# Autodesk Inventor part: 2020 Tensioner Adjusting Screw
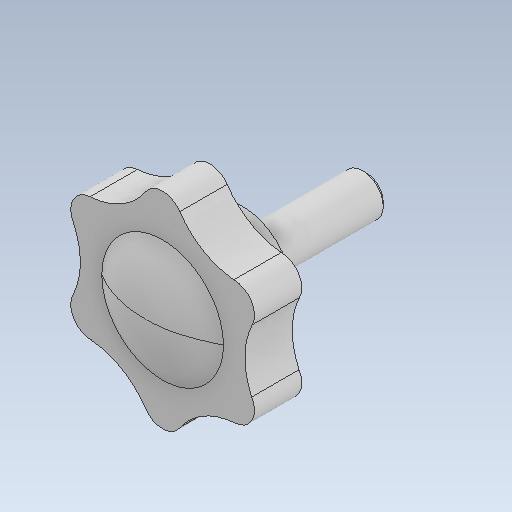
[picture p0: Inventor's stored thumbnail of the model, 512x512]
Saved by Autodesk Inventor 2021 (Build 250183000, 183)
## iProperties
Created: 2023-10
Part Number: 2020 Tensioner Adjusting Screw
Material: Generico
Document SubType Name: Modeling
Designer: hp
Density: 1 g/cm^3
Appearance: Default
Author: hp
Revision Number: ANY
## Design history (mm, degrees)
feature "Solido1"
body "Solid1"
